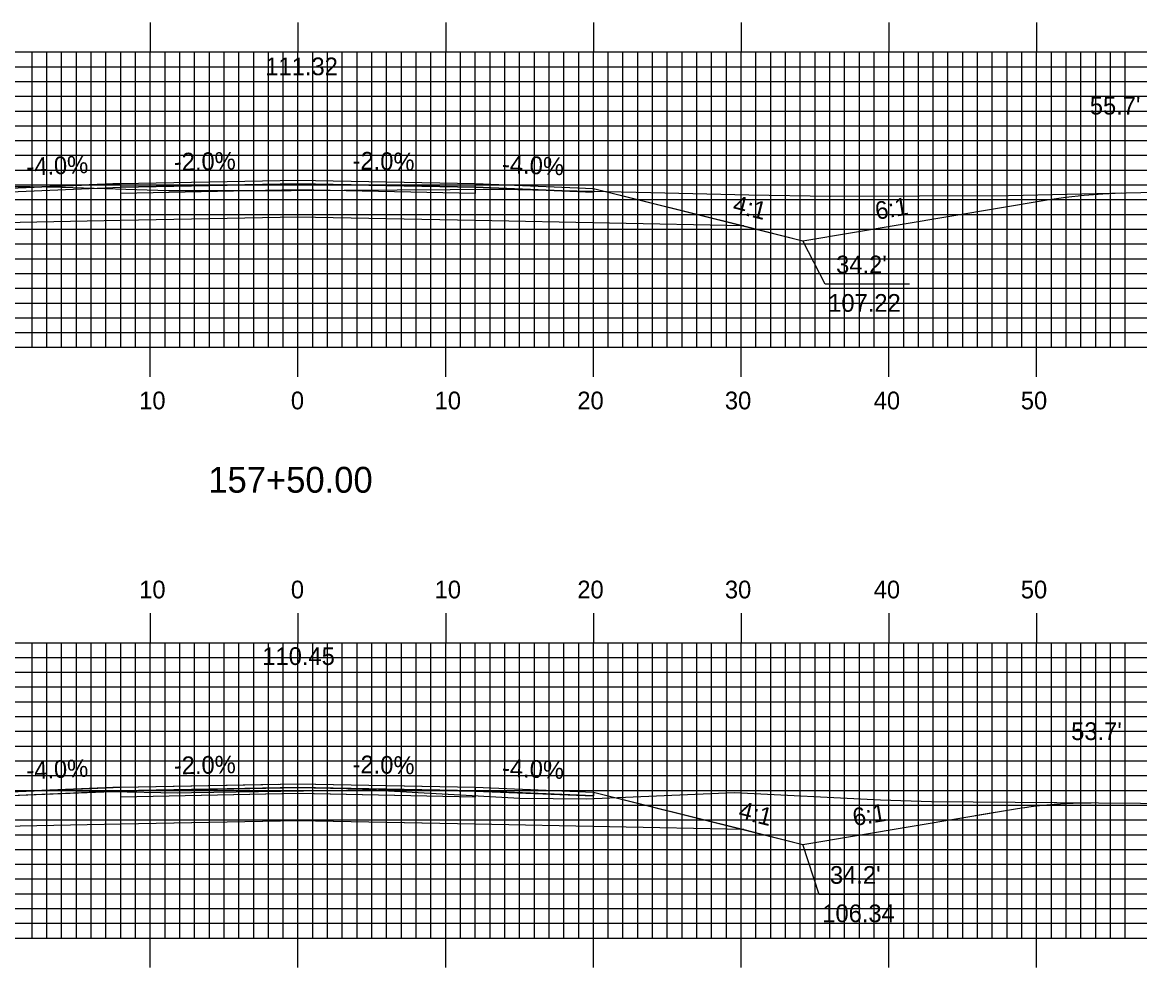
# Model space of a CAD drawing. Extents: x 1779499 to 1779842, y 442591 to 442811.
# Drawn here: x 1779646.2 to 1779721.8, y 442646.7 to 442710.7 of the extents above; entities that cross this region are included whole.
import ezdxf

# ---------------------------------------------------------------- set-up
doc = ezdxf.new("R2010")
doc.units = 0
for name, color, linetype in [('ANNOTATION', 7, 'Continuous'), ('D_Roadway_Centerline', 7, 'Continuous'), ('D_Roadway_Centerline_Text', 7, 'Continuous'), ('D_Roadway_Edge_Shoulder', 7, 'Continuous'), ('D_Roadway_Edge_TW', 7, 'Continuous'), ('D_Roadway_Pavement', 7, 'Continuous'), ('D_Roadway_SlopeLines', 7, 'Continuous'), ('D_Roadway_SubGrade', 7, 'Continuous'), ('D_Text_Standard', 7, 'Continuous'), ('H_V ANNOTATION', 7, 'Continuous'), ('MAJOR', 7, 'Continuous'), ('MINOR', 7, 'Continuous'), ('S_Roadway_Centerline', 7, 'Continuous')]:
    doc.layers.add(name, color=color, linetype=linetype)

msp = doc.modelspace()

# ---------------------------------------------------------------- linework, layer by layer
at = {"layer": 'ANNOTATION'}
for points in [[(1779706.227, 442692.944), (1779700.535, 442692.944), (1779699.016, 442695.884)], [(1779705.809, 442651.613), (1779700.117, 442651.613), (1779699.016, 442655.009)]]:
    msp.add_lwpolyline(points, dxfattribs=at)
at = {"layer": 'D_Roadway_Centerline'}
for points in [[(1779601.841, 442700.306), (1779603.091, 442700.265), (1779604.341, 442700.176), (1779605.591, 442700.04), (1779606.841, 442699.855), (1779630.668, 442695.884), (1779634.668, 442696.884), (1779644.842, 442699.428), (1779652.842, 442699.748), (1779664.842, 442699.988), (1779676.842, 442699.748), (1779684.842, 442699.428), (1779695.016, 442696.884), (1779699.016, 442695.884), (1779715.566, 442698.643), (1779716.816, 442698.829), (1779718.066, 442698.97), (1779719.316, 442699.067), (1779720.566, 442699.12)], [(1779606.661, 442658.631), (1779607.911, 442658.589), (1779609.161, 442658.499), (1779610.411, 442658.362), (1779611.661, 442658.177), (1779630.668, 442655.009), (1779634.668, 442656.009), (1779644.842, 442658.553), (1779652.842, 442658.873), (1779664.842, 442659.113), (1779676.842, 442658.873), (1779684.842, 442658.553), (1779695.016, 442656.009), (1779699.016, 442655.009), (1779713.537, 442657.429), (1779714.787, 442657.61), (1779716.037, 442657.737), (1779717.287, 442657.809), (1779718.537, 442657.827)], [(1779649.731, 442658.748), (1779652.842, 442658.872), (1779663.496, 442659.085)], [(1779689.076, 442657.494), (1779695.016, 442656.009), (1779696.676, 442655.594)], [(1779710.686, 442656.954), (1779713.537, 442657.429), (1779714.206, 442657.526)], [(1779717.271, 442657.808), (1779717.287, 442657.809), (1779717.312, 442657.81)]]:
    msp.add_lwpolyline(points, dxfattribs=at)
at = {"layer": 'D_Roadway_Edge_Shoulder'}
for points in [[(1779652.842, 442699.748), (1779644.842, 442699.428), (1779644.842, 442699.178), (1779652.842, 442699.498)], [(1779676.842, 442699.748), (1779684.842, 442699.428), (1779684.842, 442699.178), (1779676.842, 442699.498)], [(1779652.842, 442658.873), (1779644.842, 442658.553), (1779644.842, 442658.303), (1779652.842, 442658.623)], [(1779652.842, 442658.872), (1779644.843, 442658.552), (1779644.843, 442658.302), (1779652.842, 442658.622)], [(1779676.842, 442658.873), (1779684.842, 442658.553), (1779684.842, 442658.303), (1779676.842, 442658.623)], [(1779676.842, 442658.872), (1779684.842, 442658.552), (1779684.842, 442658.302), (1779676.842, 442658.622)]]:
    msp.add_lwpolyline(points, close=True, dxfattribs=at)
at = {"layer": 'D_Roadway_Edge_TW'}
for points in [[(1779652.842, 442699.498), (1779652.842, 442699.748), (1779664.842, 442699.988), (1779676.842, 442699.748), (1779676.842, 442699.498), (1779664.842, 442699.738)], [(1779652.842, 442658.623), (1779652.842, 442658.873), (1779664.842, 442659.113), (1779676.842, 442658.873), (1779676.842, 442658.623), (1779664.842, 442658.863)], [(1779652.842, 442658.622), (1779652.842, 442658.872), (1779664.843, 442659.112), (1779676.842, 442658.872), (1779676.842, 442658.622), (1779664.843, 442658.862)]]:
    msp.add_lwpolyline(points, close=True, dxfattribs=at)
at = {"layer": 'D_Roadway_Pavement'}
for points in [[(1779652.842, 442699.081), (1779652.842, 442699.498), (1779664.842, 442699.738), (1779676.842, 442699.498), (1779676.842, 442699.081), (1779664.842, 442699.321)], [(1779652.842, 442658.206), (1779652.842, 442658.623), (1779664.842, 442658.863), (1779676.842, 442658.623), (1779676.842, 442658.206), (1779664.842, 442658.446)], [(1779652.842, 442658.206), (1779652.842, 442658.622), (1779664.843, 442658.862), (1779676.842, 442658.622), (1779676.842, 442658.206), (1779664.843, 442658.446)]]:
    msp.add_lwpolyline(points, close=True, dxfattribs=at)
at = {"layer": 'D_Roadway_SlopeLines'}
for points in [[(1779684.842, 442699.428), (1779699.016, 442695.884)], [(1779699.016, 442695.884), (1779715.566, 442698.643), (1779716.816, 442698.829), (1779718.066, 442698.97), (1779719.316, 442699.067), (1779720.566, 442699.12)], [(1779684.842, 442658.553), (1779699.016, 442655.009)], [(1779684.842, 442658.552), (1779699.016, 442655.009)], [(1779699.016, 442655.009), (1779713.537, 442657.429), (1779714.787, 442657.61), (1779716.037, 442657.737), (1779717.287, 442657.809), (1779718.537, 442657.827)], [(1779699.016, 442655.009), (1779713.537, 442657.429), (1779714.787, 442657.61), (1779716.037, 442657.737), (1779717.287, 442657.809), (1779718.537, 442657.827)]]:
    msp.add_lwpolyline(points, dxfattribs=at)
at = {"layer": 'D_Roadway_SubGrade'}
for points in [[(1779652.842, 442697.248), (1779634.668, 442696.884), (1779644.842, 442699.428), (1779644.842, 442699.178), (1779652.842, 442699.498), (1779664.842, 442699.738), (1779676.842, 442699.498), (1779684.842, 442699.178), (1779684.842, 442699.428), (1779695.016, 442696.884), (1779676.842, 442697.248), (1779664.842, 442697.488)], [(1779652.842, 442656.373), (1779634.668, 442656.009), (1779644.842, 442658.553), (1779644.842, 442658.303), (1779652.842, 442658.623), (1779664.842, 442658.863), (1779676.842, 442658.623), (1779684.842, 442658.303), (1779684.842, 442658.553), (1779695.016, 442656.009), (1779676.842, 442656.373), (1779664.842, 442656.613)], [(1779652.842, 442656.372), (1779634.669, 442656.009), (1779644.843, 442658.552), (1779644.843, 442658.302), (1779652.842, 442658.622), (1779664.843, 442658.862), (1779676.842, 442658.622), (1779684.842, 442658.302), (1779684.842, 442658.552), (1779695.016, 442656.009), (1779676.842, 442656.372), (1779664.843, 442656.612)]]:
    msp.add_lwpolyline(points, close=True, dxfattribs=at)
at = {"layer": 'MAJOR'}
for p, q in [((1779654.842, 442710.669), (1779654.842, 442708.665)), ((1779664.842, 442710.669), (1779664.842, 442708.665)), ((1779674.842, 442710.669), (1779674.842, 442708.665)), ((1779684.842, 442710.669), (1779684.842, 442708.665)), ((1779694.842, 442710.669), (1779694.842, 442708.665)), ((1779704.842, 442710.669), (1779704.842, 442708.665)), ((1779714.842, 442710.669), (1779714.842, 442708.665)), ((1779524.842, 442708.665), (1779804.842, 442708.665)), ((1779524.842, 442708.665), (1779804.842, 442708.665)), ((1779654.842, 442688.665), (1779654.842, 442708.665)), ((1779664.842, 442688.665), (1779664.842, 442708.665)), ((1779674.842, 442688.665), (1779674.842, 442708.665)), ((1779684.842, 442688.665), (1779684.842, 442708.665)), ((1779694.842, 442688.665), (1779694.842, 442708.665)), ((1779704.842, 442688.665), (1779704.842, 442708.665)), ((1779714.842, 442688.665), (1779714.842, 442708.665)), ((1779524.842, 442703.665), (1779804.842, 442703.665)), ((1779524.842, 442698.665), (1779804.842, 442698.665)), ((1779524.842, 442693.665), (1779804.842, 442693.665)), ((1779524.842, 442688.665), (1779804.842, 442688.665)), ((1779524.842, 442688.665), (1779804.842, 442688.665)), ((1779654.842, 442686.661), (1779654.842, 442688.665)), ((1779664.842, 442686.661), (1779664.842, 442688.665)), ((1779674.842, 442686.661), (1779674.842, 442688.665)), ((1779684.842, 442686.661), (1779684.842, 442688.665)), ((1779694.842, 442686.661), (1779694.842, 442688.665)), ((1779704.842, 442686.661), (1779704.842, 442688.665)), ((1779714.842, 442686.661), (1779714.842, 442688.665)), ((1779654.842, 442670.669), (1779654.842, 442668.665)), ((1779664.842, 442670.669), (1779664.842, 442668.665)), ((1779674.842, 442670.669), (1779674.842, 442668.665)), ((1779684.842, 442670.669), (1779684.842, 442668.665)), ((1779694.842, 442670.669), (1779694.842, 442668.665)), ((1779704.842, 442670.669), (1779704.842, 442668.665)), ((1779714.842, 442670.669), (1779714.842, 442668.665)), ((1779524.842, 442668.665), (1779804.842, 442668.665)), ((1779524.842, 442668.665), (1779804.842, 442668.665)), ((1779654.842, 442648.665), (1779654.842, 442668.665)), ((1779664.842, 442648.665), (1779664.842, 442668.665)), ((1779674.842, 442648.665), (1779674.842, 442668.665)), ((1779684.842, 442648.665), (1779684.842, 442668.665)), ((1779694.842, 442648.665), (1779694.842, 442668.665)), ((1779704.842, 442648.665), (1779704.842, 442668.665)), ((1779714.842, 442648.665), (1779714.842, 442668.665)), ((1779524.842, 442663.665), (1779804.842, 442663.665)), ((1779524.842, 442658.665), (1779804.842, 442658.665)), ((1779524.842, 442653.665), (1779804.842, 442653.665)), ((1779524.842, 442648.665), (1779804.842, 442648.665)), ((1779524.842, 442648.665), (1779804.842, 442648.665)), ((1779654.842, 442646.661), (1779654.842, 442648.665)), ((1779664.842, 442646.661), (1779664.842, 442648.665)), ((1779674.842, 442646.661), (1779674.842, 442648.665)), ((1779684.842, 442646.661), (1779684.842, 442648.665)), ((1779694.842, 442646.661), (1779694.842, 442648.665)), ((1779704.842, 442646.661), (1779704.842, 442648.665)), ((1779714.842, 442646.661), (1779714.842, 442648.665))]:
    msp.add_line(p, q, dxfattribs=at)
at = {"layer": 'MINOR'}
for p, q in [((1779646.842, 442688.665), (1779646.842, 442708.665)), ((1779647.842, 442688.665), (1779647.842, 442708.665)), ((1779648.842, 442688.665), (1779648.842, 442708.665)), ((1779649.842, 442688.665), (1779649.842, 442708.665)), ((1779650.842, 442688.665), (1779650.842, 442708.665)), ((1779651.842, 442688.665), (1779651.842, 442708.665)), ((1779652.842, 442688.665), (1779652.842, 442708.665)), ((1779653.842, 442688.665), (1779653.842, 442708.665)), ((1779655.842, 442688.665), (1779655.842, 442708.665)), ((1779656.842, 442688.665), (1779656.842, 442708.665)), ((1779657.842, 442688.665), (1779657.842, 442708.665)), ((1779658.842, 442688.665), (1779658.842, 442708.665)), ((1779659.842, 442688.665), (1779659.842, 442708.665)), ((1779660.842, 442688.665), (1779660.842, 442708.665)), ((1779661.842, 442688.665), (1779661.842, 442708.665)), ((1779662.842, 442688.665), (1779662.842, 442708.665)), ((1779663.842, 442688.665), (1779663.842, 442708.665)), ((1779665.842, 442688.665), (1779665.842, 442708.665)), ((1779666.842, 442688.665), (1779666.842, 442708.665)), ((1779667.842, 442688.665), (1779667.842, 442708.665)), ((1779668.842, 442688.665), (1779668.842, 442708.665)), ((1779669.842, 442688.665), (1779669.842, 442708.665)), ((1779670.842, 442688.665), (1779670.842, 442708.665)), ((1779671.842, 442688.665), (1779671.842, 442708.665)), ((1779672.842, 442688.665), (1779672.842, 442708.665)), ((1779673.842, 442688.665), (1779673.842, 442708.665)), ((1779675.842, 442688.665), (1779675.842, 442708.665)), ((1779676.842, 442688.665), (1779676.842, 442708.665)), ((1779677.842, 442688.665), (1779677.842, 442708.665)), ((1779678.842, 442688.665), (1779678.842, 442708.665)), ((1779679.842, 442688.665), (1779679.842, 442708.665)), ((1779680.842, 442688.665), (1779680.842, 442708.665)), ((1779681.842, 442688.665), (1779681.842, 442708.665)), ((1779682.842, 442688.665), (1779682.842, 442708.665)), ((1779683.842, 442688.665), (1779683.842, 442708.665)), ((1779685.842, 442688.665), (1779685.842, 442708.665)), ((1779686.842, 442688.665), (1779686.842, 442708.665)), ((1779687.842, 442688.665), (1779687.842, 442708.665)), ((1779688.842, 442688.665), (1779688.842, 442708.665)), ((1779689.842, 442688.665), (1779689.842, 442708.665)), ((1779690.842, 442688.665), (1779690.842, 442708.665)), ((1779691.842, 442688.665), (1779691.842, 442708.665)), ((1779692.842, 442688.665), (1779692.842, 442708.665)), ((1779693.842, 442688.665), (1779693.842, 442708.665)), ((1779695.842, 442688.665), (1779695.842, 442708.665)), ((1779696.842, 442688.665), (1779696.842, 442708.665)), ((1779697.842, 442688.665), (1779697.842, 442708.665)), ((1779698.842, 442688.665), (1779698.842, 442708.665)), ((1779699.842, 442688.665), (1779699.842, 442708.665)), ((1779700.842, 442688.665), (1779700.842, 442708.665)), ((1779701.842, 442688.665), (1779701.842, 442708.665)), ((1779702.842, 442688.665), (1779702.842, 442708.665)), ((1779703.842, 442688.665), (1779703.842, 442708.665)), ((1779705.842, 442688.665), (1779705.842, 442708.665)), ((1779706.842, 442688.665), (1779706.842, 442708.665)), ((1779707.842, 442688.665), (1779707.842, 442708.665)), ((1779708.842, 442688.665), (1779708.842, 442708.665)), ((1779709.842, 442688.665), (1779709.842, 442708.665)), ((1779710.842, 442688.665), (1779710.842, 442708.665)), ((1779711.842, 442688.665), (1779711.842, 442708.665)), ((1779712.842, 442688.665), (1779712.842, 442708.665)), ((1779713.842, 442688.665), (1779713.842, 442708.665)), ((1779715.842, 442688.665), (1779715.842, 442708.665)), ((1779716.842, 442688.665), (1779716.842, 442708.665)), ((1779717.842, 442688.665), (1779717.842, 442708.665)), ((1779718.842, 442688.665), (1779718.842, 442708.665)), ((1779719.842, 442688.665), (1779719.842, 442708.665)), ((1779720.842, 442688.665), (1779720.842, 442708.665)), ((1779524.842, 442707.665), (1779804.842, 442707.665)), ((1779524.842, 442706.665), (1779804.842, 442706.665)), ((1779524.842, 442705.665), (1779804.842, 442705.665)), ((1779524.842, 442704.665), (1779804.842, 442704.665)), ((1779524.842, 442702.665), (1779804.842, 442702.665)), ((1779524.842, 442701.665), (1779804.842, 442701.665)), ((1779524.842, 442700.665), (1779804.842, 442700.665)), ((1779524.842, 442699.665), (1779804.842, 442699.665)), ((1779524.842, 442697.665), (1779804.842, 442697.665)), ((1779524.842, 442696.665), (1779804.842, 442696.665)), ((1779524.842, 442695.665), (1779804.842, 442695.665)), ((1779524.842, 442694.665), (1779804.842, 442694.665)), ((1779524.842, 442692.665), (1779804.842, 442692.665)), ((1779524.842, 442691.665), (1779804.842, 442691.665)), ((1779524.842, 442690.665), (1779804.842, 442690.665)), ((1779524.842, 442689.665), (1779804.842, 442689.665)), ((1779646.842, 442648.665), (1779646.842, 442668.665)), ((1779647.842, 442648.665), (1779647.842, 442668.665)), ((1779648.842, 442648.665), (1779648.842, 442668.665)), ((1779649.842, 442648.665), (1779649.842, 442668.665)), ((1779650.842, 442648.665), (1779650.842, 442668.665)), ((1779651.842, 442648.665), (1779651.842, 442668.665)), ((1779652.842, 442648.665), (1779652.842, 442668.665)), ((1779653.842, 442648.665), (1779653.842, 442668.665)), ((1779655.842, 442648.665), (1779655.842, 442668.665)), ((1779656.842, 442648.665), (1779656.842, 442668.665)), ((1779657.842, 442648.665), (1779657.842, 442668.665)), ((1779658.842, 442648.665), (1779658.842, 442668.665)), ((1779659.842, 442648.665), (1779659.842, 442668.665)), ((1779660.842, 442648.665), (1779660.842, 442668.665)), ((1779661.842, 442648.665), (1779661.842, 442668.665)), ((1779662.842, 442648.665), (1779662.842, 442668.665)), ((1779663.842, 442648.665), (1779663.842, 442668.665)), ((1779665.842, 442648.665), (1779665.842, 442668.665)), ((1779666.842, 442648.665), (1779666.842, 442668.665)), ((1779667.842, 442648.665), (1779667.842, 442668.665)), ((1779668.842, 442648.665), (1779668.842, 442668.665)), ((1779669.842, 442648.665), (1779669.842, 442668.665)), ((1779670.842, 442648.665), (1779670.842, 442668.665)), ((1779671.842, 442648.665), (1779671.842, 442668.665)), ((1779672.842, 442648.665), (1779672.842, 442668.665)), ((1779673.842, 442648.665), (1779673.842, 442668.665)), ((1779675.842, 442648.665), (1779675.842, 442668.665)), ((1779676.842, 442648.665), (1779676.842, 442668.665)), ((1779677.842, 442648.665), (1779677.842, 442668.665)), ((1779678.842, 442648.665), (1779678.842, 442668.665)), ((1779679.842, 442648.665), (1779679.842, 442668.665)), ((1779680.842, 442648.665), (1779680.842, 442668.665)), ((1779681.842, 442648.665), (1779681.842, 442668.665)), ((1779682.842, 442648.665), (1779682.842, 442668.665)), ((1779683.842, 442648.665), (1779683.842, 442668.665)), ((1779685.842, 442648.665), (1779685.842, 442668.665)), ((1779686.842, 442648.665), (1779686.842, 442668.665)), ((1779687.842, 442648.665), (1779687.842, 442668.665)), ((1779688.842, 442648.665), (1779688.842, 442668.665)), ((1779689.842, 442648.665), (1779689.842, 442668.665)), ((1779690.842, 442648.665), (1779690.842, 442668.665)), ((1779691.842, 442648.665), (1779691.842, 442668.665)), ((1779692.842, 442648.665), (1779692.842, 442668.665)), ((1779693.842, 442648.665), (1779693.842, 442668.665)), ((1779695.842, 442648.665), (1779695.842, 442668.665)), ((1779696.842, 442648.665), (1779696.842, 442668.665)), ((1779697.842, 442648.665), (1779697.842, 442668.665)), ((1779698.842, 442648.665), (1779698.842, 442668.665)), ((1779699.842, 442648.665), (1779699.842, 442668.665)), ((1779700.842, 442648.665), (1779700.842, 442668.665)), ((1779701.842, 442648.665), (1779701.842, 442668.665)), ((1779702.842, 442648.665), (1779702.842, 442668.665)), ((1779703.842, 442648.665), (1779703.842, 442668.665)), ((1779705.842, 442648.665), (1779705.842, 442668.665)), ((1779706.842, 442648.665), (1779706.842, 442668.665)), ((1779707.842, 442648.665), (1779707.842, 442668.665)), ((1779708.842, 442648.665), (1779708.842, 442668.665)), ((1779709.842, 442648.665), (1779709.842, 442668.665)), ((1779710.842, 442648.665), (1779710.842, 442668.665)), ((1779711.842, 442648.665), (1779711.842, 442668.665)), ((1779712.842, 442648.665), (1779712.842, 442668.665)), ((1779713.842, 442648.665), (1779713.842, 442668.665)), ((1779715.842, 442648.665), (1779715.842, 442668.665)), ((1779716.842, 442648.665), (1779716.842, 442668.665)), ((1779717.842, 442648.665), (1779717.842, 442668.665)), ((1779718.842, 442648.665), (1779718.842, 442668.665)), ((1779719.842, 442648.665), (1779719.842, 442668.665)), ((1779720.842, 442648.665), (1779720.842, 442668.665)), ((1779524.842, 442667.665), (1779804.842, 442667.665)), ((1779524.842, 442666.665), (1779804.842, 442666.665)), ((1779524.842, 442665.665), (1779804.842, 442665.665)), ((1779524.842, 442664.665), (1779804.842, 442664.665)), ((1779524.842, 442662.665), (1779804.842, 442662.665)), ((1779524.842, 442661.665), (1779804.842, 442661.665)), ((1779524.842, 442660.665), (1779804.842, 442660.665)), ((1779524.842, 442659.665), (1779804.842, 442659.665)), ((1779524.842, 442657.665), (1779804.842, 442657.665)), ((1779524.842, 442656.665), (1779804.842, 442656.665)), ((1779524.842, 442655.665), (1779804.842, 442655.665)), ((1779524.842, 442654.665), (1779804.842, 442654.665)), ((1779524.842, 442652.665), (1779804.842, 442652.665)), ((1779524.842, 442651.665), (1779804.842, 442651.665)), ((1779524.842, 442650.665), (1779804.842, 442650.665)), ((1779524.842, 442649.665), (1779804.842, 442649.665))]:
    msp.add_line(p, q, dxfattribs=at)
at = {"layer": 'S_Roadway_Centerline'}
for points in [[(1779524.842, 442700.977), (1779542.067, 442701.209), (1779543.7, 442701.232), (1779545.734, 442701.167), (1779564.524, 442700.548), (1779578.323, 442700.892), (1779587.234, 442700.782), (1779589.842, 442700.56), (1779592.774, 442700.519), (1779602.148, 442700.299), (1779609.242, 442700.212), (1779617.642, 442700.192), (1779633.751, 442699.89), (1779636.777, 442699.802), (1779640.225, 442699.696), (1779648.879, 442699.52), (1779656.077, 442699.28), (1779664.381, 442699.285), (1779678.738, 442699.371), (1779688.72, 442699.143), (1779695.352, 442698.99), (1779700.893, 442698.901), (1779712.939, 442698.935), (1779723.893, 442699.2)], [(1779524.842, 442659.876), (1779539.981, 442659.456), (1779542.332, 442659.471), (1779544.971, 442659.371), (1779563.612, 442659.176), (1779567.847, 442659.178), (1779578.002, 442659.476), (1779588.471, 442658.908), (1779590.47, 442658.874), (1779613.363, 442658.531), (1779613.974, 442658.519), (1779633.708, 442658.202), (1779633.943, 442658.196), (1779634.255, 442658.208), (1779647.624, 442658.69), (1779656.692, 442658.51), (1779657.627, 442658.513), (1779669.743, 442658.695), (1779679.849, 442658.136), (1779684.372, 442658.083), (1779694.365, 442658.528), (1779704.273, 442658.023), (1779707.725, 442657.909), (1779724.688, 442657.781)]]:
    msp.add_lwpolyline(points, dxfattribs=at)

# ---------------------------------------------------------------- texts
at = {"layer": 'ANNOTATION'}
for s, rotation, p in [('-4.0%', 2.29061, (1779646.474, 442700.295)), ('-2.0%', 1.14576, (1779656.448, 442700.62)), ('-2.0%', 358.85424, (1779668.528, 442700.714)), ('-4.0%', 357.70939, (1779678.634, 442700.478)), ('4:1', 345.96376, (1779694.202, 442697.822)), ('6:1', 9.46251, (1779704.015, 442697.298)), ('-4.0%', 2.29061, (1779646.474, 442659.42)), ('-2.0%', 1.14576, (1779656.448, 442659.745)), ('-2.0%', 358.85424, (1779668.528, 442659.839)), ('-4.0%', 357.70939, (1779678.634, 442659.603)), ('4:1', 345.96618, (1779694.594, 442656.783)), ('6:1', 9.46251, (1779702.493, 442656.242))]:
    msp.add_text(s, height=1.2, rotation=rotation, dxfattribs=at).set_placement(p)
for s, p in [("34.2'", (1779701.27, 442693.67)), ('107.22', (1779700.734, 442691.07)), ("34.2'", (1779700.852, 442652.339)), ('106.34', (1779700.333, 442649.739))]:
    msp.add_text(s, height=1.2, dxfattribs=at).set_placement(p)
at = {"layer": 'D_Roadway_Centerline'}
for s, p in [('C', (1779664.837, 442699.988)), ('L', (1779664.842, 442699.98)), ('C', (1779664.837, 442659.113)), ('C', (1779664.838, 442659.112)), ('L', (1779664.842, 442659.105)), ('L', (1779664.843, 442659.105))]:
    msp.add_text(s, height=0.0146, dxfattribs=at).set_placement(p)
at = {"layer": 'D_Roadway_Centerline_Text'}
for s, p in [('111.32', (1779662.633, 442707.087)), ('110.45', (1779662.429, 442667.156))]:
    msp.add_text(s, height=1.2, dxfattribs=at).set_placement(p)
at = {"layer": 'D_Text_Standard'}
for s, p in [("55.7'", (1779718.442, 442704.428)), ("53.7'", (1779717.179, 442662.073))]:
    msp.add_text(s, height=1.2, dxfattribs=at).set_placement(p)
at = {"layer": 'H_V ANNOTATION'}
for s, height, p in [('10', 1.2, (1779654.093, 442684.465)), ('0', 1.2, (1779664.36, 442684.465)), ('10', 1.2, (1779674.093, 442684.465)), ('20', 1.2, (1779683.75, 442684.465)), ('30', 1.2, (1779693.74, 442684.465)), ('40', 1.2, (1779703.815, 442684.465)), ('50', 1.2, (1779713.772, 442684.465)), ('157+50.00', 1.75, (1779658.771, 442678.821)), ('10', 1.2, (1779654.093, 442671.665)), ('0', 1.2, (1779664.36, 442671.665)), ('10', 1.2, (1779674.093, 442671.665)), ('20', 1.2, (1779683.75, 442671.665)), ('30', 1.2, (1779693.74, 442671.665)), ('40', 1.2, (1779703.815, 442671.665)), ('50', 1.2, (1779713.772, 442671.665))]:
    msp.add_text(s, height=height, dxfattribs=at).set_placement(p)

doc.saveas('drawing.dxf')
